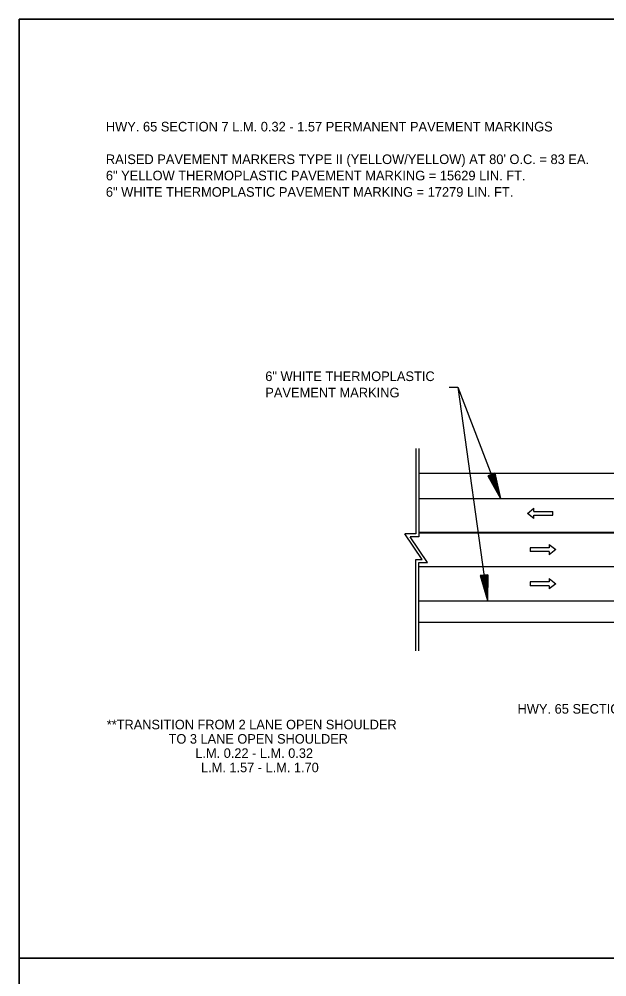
# Model space of a CAD drawing. Extents: x 1373096 to 1373266, y 381130 to 381790.
# Drawn here: x 1373096 to 1373164.8, y 381568 to 381680.2 of the extents above; entities that cross this region are included whole.
import ezdxf

# ---------------------------------------------------------------- set-up
doc = ezdxf.new("R2010")
doc.units = 0
for name, color, linetype in [('Default', 7, 'Continuous'), ('DSN_DRFT_Junk-No-Plot', 7, 'Continuous'), ('R_Draft', 7, 'Continuous'), ('SHET_Border-Text', 7, 'Continuous')]:
    doc.layers.add(name, color=color, linetype=linetype)

msp = doc.modelspace()

# ---------------------------------------------------------------- linework, layer by layer
at = {"layer": 'Default'}
for p, q in [((1373146.35, 381637.08), (1373147.35, 381637.08)), ((1373147.35, 381637.08), (1373152.36, 381624.04)), ((1373147.35, 381637.08), (1373150.81, 381612.07)), ((1373142.44, 381629.87), (1373142.44, 381619.87)), ((1373142.78, 381629.87), (1373142.78, 381619.54)), ((1373151.7, 381627), (1373150.86, 381626.68)), ((1373151.49, 381626.92), (1373151.82, 381625.45)), ((1373151.56, 381626.94), (1373151.99, 381624.99)), ((1373151.63, 381626.97), (1373152.18, 381624.5)), ((1373151.7, 381627), (1373152.36, 381624.04)), ((1373150.86, 381626.68), (1373152.36, 381624.04)), ((1373150.93, 381626.7), (1373152.18, 381624.5)), ((1373151.01, 381626.73), (1373151.99, 381624.99)), ((1373151.08, 381626.76), (1373151.82, 381625.45)), ((1373151.15, 381626.78), (1373151.63, 381625.93)), ((1373151.22, 381626.81), (1373151.45, 381626.39)), ((1373151.35, 381626.86), (1373151.45, 381626.39)), ((1373151.42, 381626.89), (1373151.63, 381625.93)), ((1373155.49, 381622.28), (1373156.26, 381622.88)), ((1373156.26, 381622.51), (1373156.26, 381622.88)), ((1373156.26, 381622.51), (1373158.47, 381622.51)), ((1373158.47, 381622.06), (1373158.47, 381622.51)), ((1373156.26, 381621.68), (1373155.49, 381622.28)), ((1373156.26, 381622.06), (1373158.47, 381622.06)), ((1373156.26, 381621.68), (1373156.26, 381622.06)), ((1373143.16, 381616.87), (1373141.16, 381619.87)), ((1373142.44, 381619.87), (1373141.16, 381619.87)), ((1373142.78, 381619.54), (1373141.78, 381619.54)), ((1373143.78, 381616.54), (1373141.78, 381619.54)), ((1373158.04, 381618.26), (1373155.83, 381618.26)), ((1373155.83, 381618.26), (1373155.83, 381617.81)), ((1373158.04, 381618.64), (1373158.04, 381618.26)), ((1373158.04, 381618.64), (1373158.81, 381618.04)), ((1373158.81, 381618.04), (1373158.04, 381617.44)), ((1373142.44, 381616.87), (1373143.16, 381616.87)), ((1373142.44, 381606.2), (1373142.44, 381616.87)), ((1373158.04, 381617.81), (1373155.83, 381617.81)), ((1373158.04, 381617.81), (1373158.04, 381617.44)), ((1373142.78, 381606.2), (1373142.78, 381616.54)), ((1373142.78, 381616.54), (1373143.78, 381616.54)), ((1373150.87, 381615.1), (1373149.97, 381614.99)), ((1373149.97, 381614.99), (1373150.81, 381612.07)), ((1373150.05, 381615), (1373150.75, 381612.57)), ((1373150.12, 381615.01), (1373150.68, 381613.08)), ((1373150.2, 381615.02), (1373150.62, 381613.57)), ((1373150.27, 381615.03), (1373150.55, 381614.08)), ((1373150.35, 381615.04), (1373150.48, 381614.58)), ((1373150.49, 381615.05), (1373150.48, 381614.58)), ((1373150.56, 381615.06), (1373150.55, 381614.08)), ((1373150.64, 381615.07), (1373150.62, 381613.57)), ((1373150.72, 381615.08), (1373150.68, 381613.08)), ((1373150.79, 381615.09), (1373150.75, 381612.57)), ((1373150.87, 381615.1), (1373150.81, 381612.07)), ((1373158.04, 381614.64), (1373158.04, 381614.26)), ((1373158.04, 381614.64), (1373158.81, 381614.04)), ((1373158.04, 381614.26), (1373155.83, 381614.26)), ((1373155.83, 381614.26), (1373155.83, 381613.81)), ((1373158.04, 381613.81), (1373155.83, 381613.81)), ((1373158.81, 381614.04), (1373158.04, 381613.44)), ((1373158.04, 381613.81), (1373158.04, 381613.44))]:
    msp.add_line(p, q, dxfattribs=at)
for points in [[(1373095.97, 381680.17), (1373095.97, 381570.17), (1373265.97, 381570.17), (1373265.97, 381680.17)], [(1373095.97, 381680.17), (1373095.97, 381570.17), (1373265.97, 381570.17), (1373265.97, 381680.17)], [(1373095.97, 381570.17), (1373095.97, 381460.17), (1373265.97, 381460.17), (1373265.97, 381570.17)]]:
    msp.add_lwpolyline(points, close=True, dxfattribs=at)
at = {"layer": 'DSN_DRFT_Junk-No-Plot'}
for points in [[(1373095.97, 381680.17), (1373265.97, 381680.17), (1373265.97, 381570.17), (1373095.97, 381570.17)], [(1373095.97, 381680.17), (1373095.97, 381570.17), (1373265.97, 381570.17), (1373265.97, 381680.17)], [(1373095.97, 381570.17), (1373265.97, 381570.17), (1373265.97, 381460.17), (1373095.97, 381460.17)], [(1373095.97, 381570.17), (1373095.97, 381460.17), (1373265.97, 381460.17), (1373265.97, 381570.17)]]:
    msp.add_lwpolyline(points, close=True, dxfattribs=at)
at = {"layer": 'R_Draft'}
for p, q in [((1373142.77, 381627.01), (1373219.16, 381627.01)), ((1373142.78, 381624.04), (1373219.17, 381624.04)), ((1373142.78, 381624.04), (1373219.17, 381624.04)), ((1373142.74, 381620.09), (1373219.14, 381620.09)), ((1373142.81, 381619.99), (1373219.2, 381619.99)), ((1373142.78, 381616.04), (1373219.17, 381616.04)), ((1373142.78, 381612.04), (1373219.17, 381612.04)), ((1373142.74, 381609.54), (1373219.13, 381609.54))]:
    msp.add_line(p, q, dxfattribs=at)

# ---------------------------------------------------------------- texts
at = {"layer": 'Default'}
for s, p in [('HWY. 65 SECTION 7 L.M. 0.32 - 1.57 PERMANENT PAVEMENT MARKINGS', (1373106.13, 381667.02)), ("RAISED PAVEMENT MARKERS TYPE II (YELLOW/YELLOW) AT 80' O.C. = 83 EA.", (1373106.13, 381663.2)), ('6" YELLOW THERMOPLASTIC PAVEMENT MARKING = 15629 LIN. FT.', (1373106.13, 381661.29)), ('6" WHITE THERMOPLASTIC PAVEMENT MARKING = 17279 LIN. FT.', (1373106.13, 381659.37)), ('6" WHITE THERMOPLASTIC', (1373124.8, 381637.78)), ('PAVEMENT MARKING', (1373124.8, 381635.87))]:
    msp.add_text(s, height=1.125, dxfattribs=at).set_placement(p)
at = {"layer": 'R_Draft'}
msp.add_text('HWY. 65 SECTION 7 L.M. 0.32 - 1.57 PERMANENT PAVEMENT MARKINGS', height=1.125, dxfattribs=at).set_placement((1373154.34, 381598.82))
at = {"layer": 'SHET_Border-Text'}
for s, p in [('**TRANSITION FROM 2 LANE OPEN SHOULDER', (1373106.24, 381596.99)), ('TO 3 LANE OPEN SHOULDER', (1373113.48, 381595.31)), ('L.M. 0.22 - L.M. 0.32', (1373116.61, 381593.64)), ('L.M. 1.57 - L.M. 1.70', (1373117.28, 381591.96))]:
    msp.add_text(s, height=1.117, dxfattribs=at).set_placement(p)

doc.saveas('drawing.dxf')
